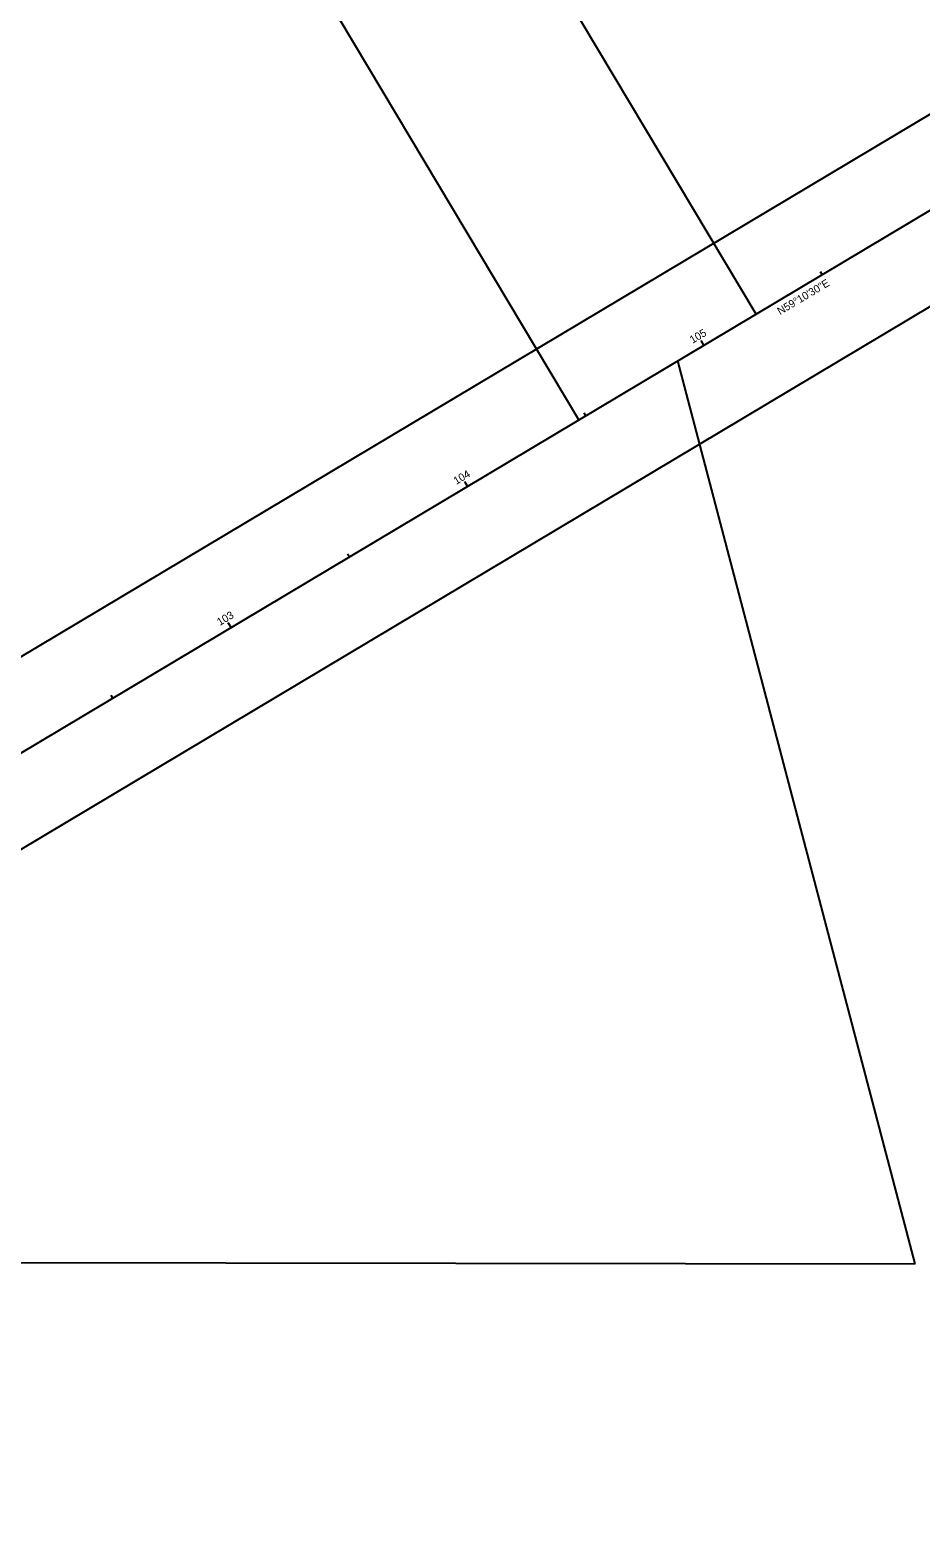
# Model space of a CAD drawing. Extents: x 2351593 to 2354159, y 766293 to 768001.
# Drawn here: x 2352600 to 2352924, y 766754 to 767301 of the extents above; entities that cross this region are included whole.
import ezdxf

# ---------------------------------------------------------------- set-up
doc = ezdxf.new("R2010")
doc.units = 0
for name, color, linetype in [('PV_X_COP', 7, 'Continuous'), ('PV_X_Driveway', 7, 'Continuous'), ('PV_X_Steps', 7, 'Continuous'), ('RD_X_Misc_Items', 7, 'Continuous'), ('SV_P_Mon_Cells_Set', 7, 'Continuous'), ('SV_X_Mon_Cells_Found', 7, 'Continuous'), ('SV_X_Shot_Marker', 7, 'Continuous')]:
    doc.layers.add(name, color=color, linetype=linetype)

msp = doc.modelspace()

# ---------------------------------------------------------------- linework, layer by layer
at = {"layer": 'PV_X_COP'}
for p, q in [((2352864.14, 767198.39), (2352707.17, 767461.44)), ((2352799.73, 767159.96), (2352632.36, 767440.46)), ((2352921.95, 766853.61), (2352835.7, 767181.42)), ((2352434.4, 766854.25), (2352921.95, 766853.61))]:
    msp.add_line(p, q, dxfattribs=at)
at = {"layer": 'RD_X_Misc_Items'}
for p, q in [((2352428.78, 766973.55), (2354128.21, 767987.61)), ((2352450.22, 766916.47), (2354158.95, 767936.09))]:
    msp.add_line(p, q, dxfattribs=at)
at = {"layer": 'SV_P_Mon_Cells_Set'}
for p, q in [((2352888.16, 767212.73), (2352887.55, 767213.76)), ((2352845.23, 767187.11), (2352844.2, 767188.83)), ((2352802.29, 767161.49), (2352801.68, 767162.52)), ((2352759.35, 767135.87), (2352758.33, 767137.58)), ((2352716.42, 767110.25), (2352715.8, 767111.28)), ((2352673.48, 767084.63), (2352672.46, 767086.34)), ((2352630.54, 767059), (2352629.93, 767060.03))]:
    msp.add_line(p, q, dxfattribs=at)
at = {"layer": 'SV_X_Mon_Cells_Found'}
msp.add_line((2351616.47, 766453.89), (2354143.58, 767961.85), dxfattribs=at)
at = {"layer": 'SV_X_Shot_Marker'}
for p, q in [((2352845.23, 767187.11), (2352844.2, 767188.83)), ((2352759.35, 767135.87), (2352758.74, 767136.9)), ((2352673.48, 767084.63), (2352672.87, 767085.66))]:
    msp.add_line(p, q, dxfattribs=at)

# ---------------------------------------------------------------- texts
at = {"layer": 'PV_X_Driveway'}
msp.add_text('N59°10\'30"E', height=2.8, rotation=30.825, dxfattribs=at).set_placement((2352872.88, 767198.02))
at = {"layer": 'PV_X_Steps'}
msp.add_text('N59°10\'30"E', height=2.8, rotation=30.825, dxfattribs=at).set_placement((2352872.88, 767198.02))
at = {"layer": 'SV_P_Mon_Cells_Set'}
for s, p in [('105', (2352841.09, 767187.61)), ('104', (2352755.27, 767136.39)), ('103', (2352669.37, 767085.14))]:
    msp.add_text(s, height=2.8, rotation=30.825, dxfattribs=at).set_placement(p)
at = {"layer": 'SV_X_Shot_Marker'}
msp.add_text('105', height=2.8, rotation=30.825, dxfattribs=at).set_placement((2352841.09, 767187.61))

doc.saveas('drawing.dxf')
